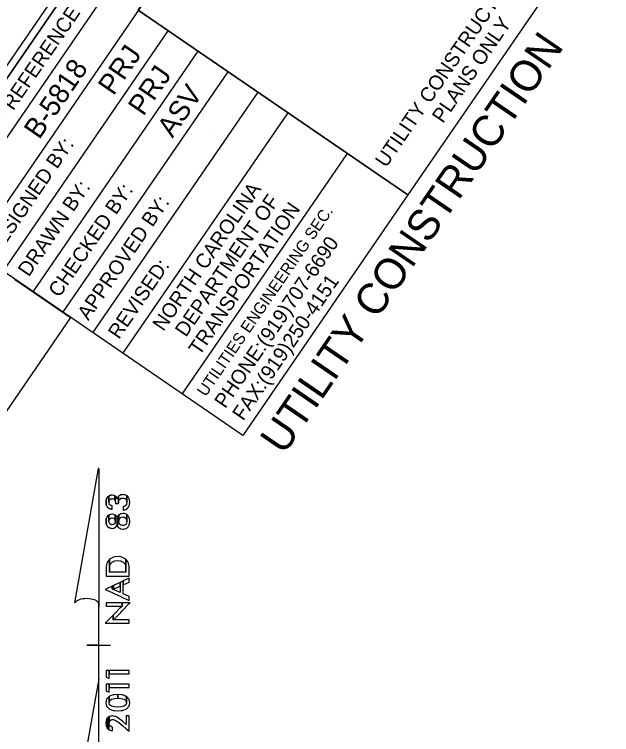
# Model space of a CAD drawing. Extents: x 1439200 to 1642184, y 394112 to 606444.
# Drawn here: x 1641794 to 1641876.4, y 394767.3 to 394866.8 of the extents above; entities that cross this region are included whole.
import ezdxf

# ---------------------------------------------------------------- set-up
doc = ezdxf.new("R2010")
doc.units = 0
for name, color, linetype in [('North Arrow NAD83 CELL', 7, 'Continuous'), ('Sheet Data Field CELL', 7, 'Continuous'), ('Sheet Plot Border Inside CELL', 7, 'Continuous'), ('Sheet Sticker Exception Certification CELL', 7, 'Continuous'), ('UC Plan Sheet 34 CELL', 7, 'Continuous')]:
    doc.layers.add(name, color=color, linetype=linetype)

msp = doc.modelspace()

# ---------------------------------------------------------------- linework, layer by layer
at = {"layer": 'North Arrow NAD83 CELL'}
for p, q in [((1641802.359, 394785.498), (1641805.647, 394804.036)), ((1641805.667, 394804.036), (1641805.647, 394804.036)), ((1641805.667, 394804.036), (1641805.647, 394804.036)), ((1641805.667, 394804.036), (1641805.659, 394784.916)), ((1641805.655, 394774.996), (1641805.659, 394785.476)), ((1641805.659, 394784.916), (1641805.659, 394785.456)), ((1641804.057, 394779.637), (1641804.037, 394779.637)), ((1641805.477, 394779.636), (1641804.057, 394779.637)), ((1641804.077, 394779.637), (1641807.277, 394779.636)), ((1641805.655, 394774.996), (1641802.307, 394756.098)), ((1641805.667, 394756.176), (1641805.655, 394774.996))]:
    msp.add_line(p, q, dxfattribs=at)
for points in [[(1641806.653, 394799.425), (1641806.695, 394799.056), (1641806.695, 394799.716)], [(1641807.455, 394798.442), (1641807.494, 394798.439), (1641807.494, 394798.91), (1641807.455, 394798.912), (1641807.34, 394798.939), (1641807.324, 394798.943), (1641807.322, 394798.944), (1641807.186, 394799.039), (1641807.18, 394799.05), (1641807.169, 394799.068), (1641807.102, 394799.187), (1641807.088, 394799.27), (1641807.084, 394799.294), (1641807.068, 394799.383), (1641807.068, 394800.249), (1641806.895, 394800.131), (1641806.847, 394800.049), (1641806.847, 394800.049), (1641806.708, 394799.809), (1641806.695, 394799.716), (1641806.695, 394799.055), (1641806.709, 394799.028), (1641806.848, 394798.746), (1641806.895, 394798.705), (1641807.068, 394798.56), (1641807.084, 394798.547), (1641807.088, 394798.545), (1641807.102, 394798.54), (1641807.169, 394798.516), (1641807.18, 394798.512), (1641807.186, 394798.51), (1641807.322, 394798.461), (1641807.324, 394798.46), (1641807.34, 394798.454)], [(1641807.815, 394799.773), (1641807.871, 394799.732), (1641807.87, 394800.28), (1641807.815, 394800.315), (1641807.711, 394800.335), (1641807.513, 394800.372), (1641807.498, 394800.375), (1641807.493, 394800.374), (1641807.454, 394800.367), (1641807.34, 394800.348), (1641807.323, 394800.345), (1641807.321, 394800.345), (1641807.321, 394800.344), (1641807.185, 394800.321), (1641807.179, 394800.32), (1641807.169, 394800.319), (1641807.102, 394800.273), (1641807.087, 394800.263), (1641807.083, 394800.26), (1641807.068, 394800.249), (1641807.068, 394799.383), (1641807.083, 394799.534), (1641807.088, 394799.575), (1641807.102, 394799.602), (1641807.169, 394799.726), (1641807.179, 394799.746), (1641807.185, 394799.75), (1641807.321, 394799.848), (1641807.323, 394799.849), (1641807.34, 394799.852), (1641807.454, 394799.874), (1641807.493, 394799.881), (1641807.499, 394799.882), (1641807.513, 394799.885), (1641807.711, 394799.85)], [(1641807.871, 394799.731), (1641807.952, 394799.566), (1641807.952, 394800.229), (1641807.87, 394800.28)], [(1641808.266, 394799.226), (1641808.393, 394799.226), (1641808.393, 394800.197), (1641808.266, 394800.029), (1641808.206, 394799.824), (1641808.166, 394799.974), (1641808.047, 394800.169), (1641807.976, 394800.213), (1641807.975, 394800.214), (1641807.952, 394800.229), (1641807.952, 394799.566), (1641807.976, 394799.373), (1641807.977, 394799.226), (1641808.047, 394799.226), (1641808.166, 394799.226), (1641808.207, 394799.226)], [(1641809.49, 394799.59), (1641809.525, 394799.417), (1641809.525, 394800.278), (1641809.49, 394800.301), (1641809.476, 394800.311), (1641809.476, 394800.31), (1641809.365, 394800.383), (1641809.348, 394800.386), (1641809.342, 394800.387), (1641809.264, 394800.401), (1641809.16, 394800.42), (1641809.149, 394800.422), (1641809.029, 394800.444), (1641808.933, 394800.431), (1641808.731, 394800.404), (1641808.704, 394800.4), (1641808.562, 394800.325), (1641808.446, 394800.264), (1641808.44, 394800.261), (1641808.399, 394800.206), (1641808.393, 394800.197), (1641808.393, 394799.329), (1641808.399, 394799.481), (1641808.44, 394799.648), (1641808.447, 394799.673), (1641808.562, 394799.832), (1641808.704, 394799.916), (1641808.731, 394799.932), (1641808.933, 394799.967), (1641809.03, 394799.958), (1641809.149, 394799.946), (1641809.16, 394799.94), (1641809.265, 394799.887), (1641809.342, 394799.848), (1641809.348, 394799.839), (1641809.366, 394799.814), (1641809.476, 394799.662)], [(1641809.916, 394799.026), (1641809.95, 394799.429), (1641809.916, 394799.613), (1641809.871, 394799.854), (1641809.76, 394800.037), (1641809.672, 394800.182), (1641809.53, 394800.275), (1641809.525, 394800.278), (1641809.525, 394799.417), (1641809.49, 394799.125), (1641809.476, 394799.103), (1641809.366, 394798.941), (1641809.348, 394798.916), (1641809.342, 394798.912), (1641809.265, 394798.871), (1641809.161, 394798.817), (1641809.15, 394798.815), (1641809.03, 394798.808), (1641809.019, 394798.807), (1641809.019, 394798.311), (1641809.03, 394798.312), (1641809.15, 394798.329), (1641809.161, 394798.331), (1641809.265, 394798.346), (1641809.342, 394798.378), (1641809.349, 394798.38), (1641809.366, 394798.388), (1641809.476, 394798.434), (1641809.491, 394798.44), (1641809.526, 394798.455), (1641809.531, 394798.457), (1641809.673, 394798.603), (1641809.761, 394798.693), (1641809.872, 394798.931)], [(1641808.104, 394796.081), (1641808.187, 394796.234), (1641808.187, 394797.287), (1641808.103, 394797.451), (1641808.099, 394797.455), (1641807.973, 394797.594), (1641807.971, 394797.596), (1641807.943, 394797.612), (1641807.943, 394796.756), (1641807.916, 394796.559), (1641807.826, 394796.405), (1641807.759, 394796.361), (1641807.759, 394796.36), (1641807.756, 394796.359), (1641807.686, 394796.312), (1641807.513, 394796.28), (1641807.452, 394796.291), (1641807.332, 394796.312), (1641807.184, 394796.422), (1641807.182, 394796.426), (1641807.135, 394796.509), (1641807.098, 394796.577), (1641807.073, 394796.764), (1641807.073, 394797.612), (1641806.88, 394797.466), (1641806.709, 394797.151), (1641806.71, 394796.374), (1641806.881, 394796.05), (1641807.074, 394795.905), (1641807.098, 394795.887), (1641807.136, 394795.859), (1641807.182, 394795.846), (1641807.184, 394795.846), (1641807.332, 394795.807), (1641807.452, 394795.776), (1641807.514, 394795.784), (1641807.686, 394795.804), (1641807.756, 394795.813), (1641807.759, 394795.814), (1641807.826, 394795.848), (1641807.916, 394795.894), (1641807.943, 394795.907), (1641807.972, 394795.921), (1641807.974, 394795.923), (1641808.1, 394796.073)], [(1641807.916, 394796.962), (1641807.943, 394796.756), (1641807.943, 394797.612), (1641807.916, 394797.626), (1641807.825, 394797.675), (1641807.758, 394797.711), (1641807.755, 394797.711), (1641807.685, 394797.719), (1641807.513, 394797.736), (1641807.513, 394797.736), (1641807.451, 394797.742), (1641807.332, 394797.71), (1641807.183, 394797.671), (1641807.181, 394797.671), (1641807.135, 394797.659), (1641807.098, 394797.63), (1641807.073, 394797.612), (1641807.073, 394796.764), (1641807.098, 394796.943), (1641807.135, 394797.013), (1641807.181, 394797.102), (1641807.183, 394797.103), (1641807.332, 394797.208), (1641807.451, 394797.229), (1641807.513, 394797.241), (1641807.685, 394797.209), (1641807.755, 394797.162), (1641807.758, 394797.159), (1641807.825, 394797.115)], [(1641809.905, 394796.363), (1641809.951, 394796.76), (1641809.904, 394797.164), (1641809.903, 394797.166), (1641809.739, 394797.52), (1641809.737, 394797.521), (1641809.53, 394797.686), (1641809.531, 394796.759), (1641809.498, 394796.512), (1641809.443, 394796.421), (1641809.443, 394796.421), (1641809.382, 394796.32), (1641809.201, 394796.206), (1641809.088, 394796.184), (1641809.085, 394796.184), (1641808.981, 394796.164), (1641808.749, 394796.206), (1641808.724, 394796.223), (1641808.558, 394796.341), (1641808.557, 394796.343), (1641808.449, 394796.537), (1641808.436, 394796.636), (1641808.429, 394796.693), (1641808.421, 394796.759), (1641808.421, 394797.643), (1641808.261, 394797.453), (1641808.262, 394796.064), (1641808.421, 394795.874), (1641808.43, 394795.864), (1641808.437, 394795.856), (1641808.449, 394795.849), (1641808.557, 394795.795), (1641808.558, 394795.794), (1641808.724, 394795.711), (1641808.749, 394795.708), (1641808.981, 394795.68), (1641809.085, 394795.668), (1641809.088, 394795.668), (1641809.201, 394795.698), (1641809.383, 394795.746), (1641809.443, 394795.763), (1641809.498, 394795.807), (1641809.531, 394795.833), (1641809.738, 394796), (1641809.74, 394796.004), (1641809.904, 394796.354)], [(1641809.498, 394797.007), (1641809.531, 394796.759), (1641809.53, 394797.686), (1641809.497, 394797.713), (1641809.443, 394797.756), (1641809.382, 394797.772), (1641809.2, 394797.82), (1641809.087, 394797.85), (1641809.084, 394797.851), (1641808.98, 394797.839), (1641808.98, 394797.839), (1641808.748, 394797.812), (1641808.723, 394797.81), (1641808.558, 394797.721), (1641808.557, 394797.721), (1641808.448, 394797.663), (1641808.436, 394797.657), (1641808.429, 394797.653), (1641808.421, 394797.643), (1641808.421, 394796.759), (1641808.429, 394796.825), (1641808.436, 394796.882), (1641808.449, 394796.981), (1641808.557, 394797.179), (1641808.558, 394797.18), (1641808.724, 394797.297), (1641808.748, 394797.315), (1641808.98, 394797.354), (1641809.084, 394797.336), (1641809.087, 394797.335), (1641809.201, 394797.315), (1641809.382, 394797.198), (1641809.443, 394797.098)], [(1641806.705, 394796.41), (1641806.71, 394796.375), (1641806.709, 394797.151), (1641806.704, 394797.141), (1641806.654, 394796.759), (1641806.654, 394796.758)], [(1641808.256, 394796.076), (1641808.262, 394796.064), (1641808.261, 394797.453), (1641808.256, 394797.447), (1641808.187, 394797.287), (1641808.187, 394796.234)], [(1641809.376, 394790.566), (1641809.394, 394790.5), (1641809.394, 394791.523), (1641809.375, 394791.547), (1641809.296, 394791.589), (1641809.053, 394791.719), (1641808.867, 394791.819), (1641808.693, 394791.843), (1641808.693, 394791.842), (1641808.281, 394791.9), (1641808.279, 394791.899), (1641807.864, 394791.841), (1641807.695, 394791.818), (1641807.504, 394791.715), (1641807.261, 394791.586), (1641807.187, 394791.546), (1641807.163, 394791.515), (1641807.151, 394791.499), (1641807.151, 394789.903), (1641807.164, 394790.499), (1641807.187, 394790.584), (1641807.261, 394790.849), (1641807.504, 394791.136), (1641807.695, 394791.229), (1641807.864, 394791.312), (1641808.279, 394791.364), (1641808.281, 394791.363), (1641808.693, 394791.313), (1641808.867, 394791.227), (1641809.053, 394791.137), (1641809.296, 394790.85)], [(1641809.859, 394789.201), (1641809.872, 394789.201), (1641809.871, 394789.899), (1641809.859, 394790.56), (1641809.719, 394791.103), (1641809.404, 394791.509), (1641809.405, 394789.716), (1641809.394, 394789.716), (1641809.376, 394789.716), (1641809.297, 394789.716), (1641809.053, 394789.716), (1641808.868, 394789.716), (1641808.694, 394789.716), (1641808.282, 394789.715), (1641808.28, 394789.715), (1641807.864, 394789.715), (1641807.695, 394789.715), (1641807.505, 394789.715), (1641807.262, 394789.715), (1641807.188, 394789.715), (1641807.164, 394789.715), (1641807.151, 394789.715), (1641807.151, 394791.499), (1641806.843, 394791.102), (1641806.704, 394790.559), (1641806.688, 394789.897), (1641806.688, 394789.2), (1641806.705, 394789.2), (1641806.844, 394789.2), (1641807.152, 394789.2), (1641807.164, 394789.2), (1641807.188, 394789.2), (1641807.262, 394789.2), (1641807.505, 394789.2), (1641807.696, 394789.2), (1641807.865, 394789.2), (1641808.28, 394789.2), (1641808.282, 394789.2), (1641808.694, 394789.2), (1641808.868, 394789.201), (1641809.054, 394789.201), (1641809.297, 394789.201), (1641809.376, 394789.201), (1641809.395, 394789.201), (1641809.405, 394789.201), (1641809.72, 394789.201)], [(1641809.394, 394790.499), (1641809.405, 394789.904), (1641809.404, 394791.509), (1641809.394, 394791.523)], [(1641809.052, 394787.993), (1641809.872, 394788.356), (1641809.872, 394788.902), (1641809.052, 394788.52)], [(1641809.053, 394786.203), (1641809.873, 394785.822), (1641809.873, 394786.366), (1641809.053, 394786.733), (1641809.052, 394788.52), (1641808.62, 394788.319), (1641808.621, 394786.926), (1641807.896, 394787.251), (1641807.894, 394787.251), (1641807.713, 394787.318), (1641807.708, 394787.319), (1641807.534, 394787.367), (1641807.533, 394787.812), (1641806.565, 394787.361), (1641807.534, 394786.91), (1641807.708, 394786.829), (1641807.713, 394786.826), (1641807.895, 394786.742), (1641807.897, 394786.741), (1641808.621, 394786.404)], [(1641807.534, 394787.367), (1641807.708, 394787.419), (1641807.708, 394787.893), (1641807.533, 394787.812)], [(1641807.896, 394787.488), (1641808.62, 394787.81), (1641808.62, 394788.319), (1641807.896, 394787.981), (1641807.894, 394787.98), (1641807.713, 394787.895), (1641807.708, 394787.893), (1641807.708, 394787.418), (1641807.713, 394787.42), (1641807.894, 394787.488)], [(1641808.69, 394785.046), (1641808.897, 394785.046), (1641808.897, 394785.521), (1641808.689, 394785.521), (1641808.512, 394785.521), (1641808.016, 394785.521), (1641807.825, 394785.521), (1641806.69, 394785.52), (1641806.69, 394785.045), (1641807.825, 394785.046), (1641808.016, 394785.046), (1641808.512, 394785.046)], [(1641809.874, 394785.394), (1641809.997, 394785.522), (1641809.874, 394785.522), (1641808.897, 394785.521), (1641808.897, 394785.046), (1641808.69, 394784.871), (1641808.513, 394784.698), (1641808.016, 394784.182), (1641807.826, 394783.984), (1641807.664, 394783.817), (1641807.664, 394783.152), (1641807.826, 394783.279), (1641808.016, 394783.459), (1641808.513, 394783.976), (1641808.69, 394784.161), (1641808.897, 394784.376)], [(1641808.898, 394782.679), (1641809.875, 394782.679), (1641809.875, 394783.153), (1641808.897, 394783.153), (1641808.69, 394783.153), (1641808.513, 394783.153), (1641808.017, 394783.152), (1641807.826, 394783.152), (1641807.664, 394783.152), (1641807.664, 394783.817), (1641806.567, 394782.678), (1641807.664, 394782.678), (1641807.826, 394782.678), (1641808.017, 394782.678), (1641808.513, 394782.679), (1641808.691, 394782.679)], [(1641806.705, 394775.234), (1641807.118, 394775.032), (1641807.118, 394776.163), (1641806.704, 394776.163)], [(1641807.118, 394775.689), (1641809.857, 394775.69), (1641809.857, 394776.164), (1641807.118, 394776.163)], [(1641806.706, 394773.359), (1641807.119, 394773.157), (1641807.118, 394774.288), (1641806.705, 394774.287)], [(1641807.118, 394773.814), (1641809.858, 394773.815), (1641809.858, 394774.289), (1641807.118, 394774.288)], [(1641807.83, 394772.297), (1641808.287, 394772.335), (1641808.287, 394772.849), (1641807.83, 394772.804), (1641807.656, 394772.788), (1641807.651, 394772.786), (1641807.651, 394772.785), (1641807.428, 394772.696), (1641807.428, 394772.695), (1641807.421, 394772.693), (1641807.162, 394772.589), (1641807.162, 394772.588), (1641807.095, 394772.561), (1641807.093, 394772.561), (1641807.087, 394772.554), (1641807.087, 394771.715), (1641807.094, 394771.737), (1641807.096, 394771.744), (1641807.163, 394771.986), (1641807.421, 394772.184), (1641807.428, 394772.19), (1641807.651, 394772.249), (1641807.656, 394772.25)], [(1641809.493, 394771.722), (1641809.499, 394771.698), (1641809.499, 394772.546), (1641809.493, 394772.553), (1641809.49, 394772.557), (1641809.423, 394772.584), (1641809.166, 394772.69), (1641809.164, 394772.691), (1641808.935, 394772.785), (1641808.931, 394772.787), (1641808.766, 394772.803), (1641808.756, 394772.804), (1641808.298, 394772.849), (1641808.292, 394772.85), (1641808.287, 394772.849), (1641808.287, 394772.334), (1641808.293, 394772.334), (1641808.298, 394772.334), (1641808.756, 394772.297), (1641808.767, 394772.297), (1641808.931, 394772.252), (1641808.936, 394772.251), (1641809.164, 394772.19), (1641809.166, 394772.188), (1641809.423, 394771.987), (1641809.49, 394771.733)], [(1641809.849, 394771.253), (1641809.941, 394771.706), (1641809.848, 394772.147), (1641809.843, 394772.171), (1641809.499, 394772.546), (1641809.499, 394771.698), (1641809.493, 394771.676), (1641809.49, 394771.665), (1641809.423, 394771.428), (1641809.167, 394771.23), (1641809.165, 394771.23), (1641809.165, 394771.229), (1641808.936, 394771.167), (1641808.932, 394771.166), (1641808.767, 394771.121), (1641808.757, 394771.118), (1641808.298, 394771.078), (1641808.293, 394771.078), (1641808.288, 394771.078), (1641807.831, 394771.118), (1641807.656, 394771.164), (1641807.651, 394771.165), (1641807.429, 394771.226), (1641807.421, 394771.228), (1641807.163, 394771.427), (1641807.096, 394771.683), (1641807.094, 394771.691), (1641807.087, 394771.715), (1641807.087, 394772.554), (1641806.748, 394772.184), (1641806.744, 394772.164), (1641806.644, 394771.71), (1641806.644, 394771.709), (1641806.745, 394771.238), (1641806.749, 394771.233), (1641807.088, 394770.867), (1641807.094, 394770.861), (1641807.096, 394770.859), (1641807.163, 394770.831), (1641807.422, 394770.724), (1641807.429, 394770.721), (1641807.651, 394770.63), (1641807.657, 394770.629), (1641807.831, 394770.611), (1641808.288, 394770.563), (1641808.293, 394770.562), (1641808.299, 394770.563), (1641808.757, 394770.609), (1641808.767, 394770.61), (1641808.932, 394770.627), (1641808.936, 394770.628), (1641809.165, 394770.721), (1641809.167, 394770.722), (1641809.424, 394770.827), (1641809.49, 394770.854), (1641809.494, 394770.856), (1641809.5, 394770.862), (1641809.844, 394771.247)], [(1641806.84, 394768.206), (1641807.075, 394767.985), (1641807.074, 394769.771), (1641806.839, 394769.567)], [(1641807.528, 394767.848), (1641807.585, 394767.843), (1641807.584, 394768.341), (1641807.528, 394768.345), (1641807.503, 394768.348), (1641807.497, 394768.35), (1641807.359, 394768.4), (1641807.345, 394768.411), (1641807.321, 394768.43), (1641807.205, 394768.519), (1641807.174, 394768.581), (1641807.115, 394768.699), (1641807.109, 394768.712), (1641807.1, 394768.958), (1641807.1, 394769.793), (1641807.074, 394769.771), (1641807.075, 394767.985), (1641807.1, 394767.973), (1641807.11, 394767.969), (1641807.116, 394767.967), (1641807.175, 394767.94), (1641807.205, 394767.927), (1641807.321, 394767.876), (1641807.346, 394767.865), (1641807.359, 394767.863), (1641807.497, 394767.851), (1641807.503, 394767.85)], [(1641809.448, 394768.11), (1641809.861, 394767.767), (1641809.86, 394769.898), (1641809.448, 394769.897), (1641809.448, 394768.687), (1641808.98, 394769.094), (1641808.435, 394769.539), (1641808.43, 394769.544), (1641808.004, 394769.795), (1641808.004, 394769.795), (1641807.993, 394769.802), (1641807.722, 394769.855), (1641807.584, 394769.883), (1641807.527, 394769.894), (1641807.502, 394769.889), (1641807.496, 394769.888), (1641807.358, 394769.858), (1641807.345, 394769.855), (1641807.32, 394769.85), (1641807.205, 394769.826), (1641807.205, 394769.825), (1641807.174, 394769.819), (1641807.115, 394769.807), (1641807.109, 394769.801), (1641807.1, 394769.793), (1641807.1, 394768.958), (1641807.109, 394768.984), (1641807.115, 394769.002), (1641807.174, 394769.171), (1641807.205, 394769.201), (1641807.32, 394769.314), (1641807.345, 394769.323), (1641807.358, 394769.327), (1641807.496, 394769.374), (1641807.503, 394769.374), (1641807.527, 394769.373), (1641807.584, 394769.372), (1641807.722, 394769.37), (1641807.993, 394769.263), (1641808.004, 394769.259), (1641808.43, 394768.959), (1641808.435, 394768.955), (1641808.98, 394768.501)], [(1641806.834, 394768.217), (1641806.84, 394768.207), (1641806.839, 394769.567), (1641806.834, 394769.562), (1641806.699, 394769.264), (1641806.683, 394769.228), (1641806.646, 394768.856), (1641806.646, 394768.855), (1641806.683, 394768.608), (1641806.699, 394768.499)]]:
    msp.add_lwpolyline(points, close=True, dxfattribs=at)
msp.add_ellipse((1641804.014, 394785.299), major_axis=(1.692, -0.013), ratio=0.461098, start_param=0.216388, end_param=2.908219, dxfattribs=at)
at = {"layer": 'Sheet Plot Border Inside CELL'}
msp.add_lwpolyline([(1641827.568, 394910.193), (1641450.574, 394360.438), (1641798.637, 394121.754), (1642175.631, 394671.51)], close=True, dxfattribs=at)
at = {"layer": 'Sheet Sticker Exception Certification CELL'}
for p, q in [((1641794.031, 394830.204), (1641801.784, 394824.887)), ((1641801.78, 394824.89), (1641756.527, 394758.901))]:
    msp.add_line(p, q, dxfattribs=at)
at = {"layer": 'UC Plan Sheet 34 CELL'}
for p, q in [((1641784.201, 394836.945), (1641829.408, 394902.869)), ((1641792.468, 394831.275), (1641815.257, 394864.507)), ((1641796.6, 394828.442), (1641819.389, 394861.674)), ((1641800.732, 394825.609), (1641823.521, 394858.84)), ((1641808.518, 394859.119), (1641808.518, 394859.119)), ((1641800.5, 394856.302), (1641800.5, 394856.302)), ((1641812.654, 394856.283), (1641812.654, 394856.283)), ((1641804.864, 394822.775), (1641827.653, 394856.007)), ((1641816.786, 394853.449), (1641816.786, 394853.449)), ((1641809, 394819.939), (1641831.788, 394853.171)), ((1641820.918, 394850.616), (1641820.918, 394850.616)), ((1641817.197, 394814.317), (1641839.986, 394847.549))]:
    msp.add_line(p, q, dxfattribs=at)
msp.add_lwpolyline([(1641825.582, 394905.493), (1641486.253, 394410.664), (1641832.634, 394173.134), (1642171.962, 394667.963)], close=True, dxfattribs=at)
for points in [[(1641780.374, 394839.569), (1641825.582, 394905.493), (1641833.523, 394900.047)], [(1641833.523, 394900.047), (1641788.316, 394834.123), (1641780.374, 394839.569)], [(1641870.739, 394874.527), (1641848.32, 394841.834), (1641811.121, 394867.343), (1641833.54, 394900.036)], [(1641811.105, 394867.355), (1641848.32, 394841.834), (1641825.531, 394808.603), (1641780.374, 394839.569)]]:
    msp.add_lwpolyline(points, dxfattribs=at)

# ---------------------------------------------------------------- texts
at = {"layer": 'Sheet Data Field CELL'}
for s, p in [('PRJ', (1641807.689, 394855.433)), ('B-5818', (1641797.452, 394849.382)), ('PRJ', (1641811.825, 394852.597)), ('ASV', (1641815.841, 394849.595))]:
    msp.add_text(s, height=2.8, rotation=55.55969, dxfattribs=at).set_placement(p)
at = {"layer": 'UC Plan Sheet 34 CELL'}
for s, height, p in [('UTILITY CONSTRUCTION', 2.00457, (1641845.308, 394845.488)), ('PROJECT REFERENCE NO.', 2.00457, (1641786.365, 394842.445)), ('PLANS ONLY', 2.0046, (1641853.151, 394851.611)), ('UTILITY CONSTRUCTION', 4.25, (1641831.194, 394805.806)), ('DESIGNED BY:', 2.00457, (1641791.562, 394833.146)), ('DRAWN BY:', 2.0046, (1641796.006, 394830.414)), ('CHECKED BY:', 2.00457, (1641800.215, 394827.551)), ('NORTH CAROLINA', 2.00457, (1641814.596, 394822.892)), ('APPROVED BY:', 2.00457, (1641804.222, 394824.385)), ('DEPARTMENT OF', 2.00457, (1641817.687, 394822.087)), ('TRANSPORTATION', 2.00457, (1641819.579, 394819.523)), ('UTILITIES ENGINEERING SEC.', 1.60366, (1641820.426, 394813.877)), ('PHONE:(919)707-6690', 2.00457, (1641823.117, 394812.23)), ('REVISED:', 2.0046, (1641808.443, 394821.788)), ('FAX:(919)250-4151', 2.00457, (1641825.595, 394810.531))]:
    msp.add_text(s, height=height, rotation=55.55969, dxfattribs=at).set_placement(p)

doc.saveas('drawing.dxf')
